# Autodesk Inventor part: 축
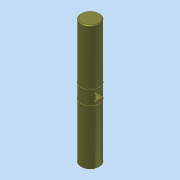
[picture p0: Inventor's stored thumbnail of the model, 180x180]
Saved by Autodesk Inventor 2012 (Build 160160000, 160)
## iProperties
Company: 한국ATC센터
Created: 2015-04
Part Number: 축
Document SubType Name: Modeling
Designer: KYOUNG IL JANG
Density: 7.85 g/cm^3
Material: 강
Author: KYOUNG IL JANG
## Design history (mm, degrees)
sketch "스케치1"
  geometry: C1 r 11 at (0, 0); 1 further point
  constraints: 1 centre point, 1 coincident
  dimensions: "d0" = 22 diameter of C1
extrude "돌출1" new body sketch "스케치1" stored distance "d1" = 150; taper "d2" = 0 deg
sketch "스케치2"
  geometry: L1 (-10.247, -4)-(10.247, -4); L2 (-10.247, 4)-(10.247, 4); A1 r 11 centre (0, 0) between (-10.247, -4) and (10.247, -4) reference; 1 further point
  constraints: 4 end point, 4 point on circle, 2 parallel, 1 horizontal
  dimensions: "d3" = 8 distance between parallel lines of L2 L1
extrude "돌출2" cut sketch "스케치2" stored distance "d4" = 8; taper "d5" = 0 deg
sketch "스케치3"
  geometry: 5 further points
hole "구멍1" sketch "스케치3" at (-4, 4), (4, 4), (4, -4), (-4, -4) diameter "d6" = 2; stored, may be unused: countersink angle "d10" = 90 deg, drill point angle "d12" = 118 deg; dims "d7" = 6, "d8" = 4, "d9" = 2, "d11" = 8
chamfer "모따기1" distance "d13" = 1; stored, may be unused: second distance "d14" = 2, angle "d15" = 45 deg
sketch "스케치4"
  geometry: L1 (-10, 9)-(-11, 9); L2 (-11, 9)-(-11, 7.8); L3 (-11, 7.8)-(-10, 7.8); L4 (-10, 7.8)-(-10, 9); L5 (-10, 75)-(10, 75) reference; L6 (0, -10)-(0, 60) reference; 1 further point
  constraints: 8 end point, 2 parallel, 1 horizontal, 1 perpendicular
  dimensions: "d16" = 7.8 distance from line of L3 point (0, 0); "d17" = 67.2 distance between parallel lines of L3 L5 (derived); "d18" = 11 distance from line of point (0, 0) L2; "d19" = 1 distance of L2.end L3.end; "d20" = 1.2 distance of L1.end L2.end
revolve "회전1" sketch "스케치4" stored, may be unused: angle "d21" = 90 deg
node "솔리드1"
mirror "대칭1"
mirror "대칭2"
